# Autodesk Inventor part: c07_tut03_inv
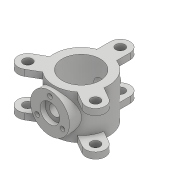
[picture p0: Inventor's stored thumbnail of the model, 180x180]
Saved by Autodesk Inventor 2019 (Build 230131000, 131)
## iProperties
Created: 2017-04
Part Number: c07_tut03_inv
Material: Generic
Document SubType Name: Modeling
Designer: CADCIM 00
Density: 1 g/cm^3
Appearance: Default
Author: CADCIM 00
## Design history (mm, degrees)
sketch "Sketch1"
  geometry: C1 r 140 at (0, 0); C2 r 97 at (0, 0); 1 further point
  constraints: 2 centre point, 2 coincident
  dimensions: "d0" = 280 diameter of C1; "d1" = 194 diameter of C2
extrude "Extrusion1" new body sketch "Sketch1" stored distance "d2" = 225; taper "d3" = 0 deg
workplane "Work Plane1"
sketch "Sketch2"
  geometry: C1 r 100 at (0, 0); 1 further point
  constraints: 1 centre point, 1 coincident
  dimensions: "d5" = 200 diameter of C1
extrude "Extrusion2" join sketch "Sketch2" stored distance "d6" = 225; taper "d7" = 0 deg
workplane "Work Plane2"
sketch "Sketch3"
  geometry: C1 r 37.5 at (0, 0); 1 further point
  constraints: 1 centre point, 1 coincident
  dimensions: "d9" = 75 diameter of C1
extrude "Extrusion3" join sketch "Sketch3" stored distance "d10" = 225; taper "d11" = 0 deg
hole "Hole1" diameter "d14" = 56; stored, may be unused: countersink angle "d18" = 90 deg, drill point angle "d20" = 0 deg; dims "d12" = 10, "d13" = 10, "d15" = 6, "d16" = 100, "d17" = 25, "d19" = 310
sketch "Sketch6"
  geometry: 2 further points
  constraints: 1 vertical alignment
  dimensions: "d21" = 75 distance of point (0, 75) point (0, 0)
hole "Hole2" sketch "Sketch6" at (0, 75) diameter "d22" = 24; stored, may be unused: countersink angle "d26" = 90 deg, drill point angle "d28" = 0 deg; dims "d23" = 6, "d24" = 100, "d25" = 25, "d27" = 15
pattern_circular "Circular Pattern1" dims angle "d30" = 360 deg
sketch "Sketch7"
  geometry: L1 (-50, 130.767)-(-50, 200); L2 (50, 200)-(50, 130.767); L3 (0, 0)-(0, 200); C1 r 23.5 at (0, 200); A1 r 50 centre (0, 200) between (50, 200) and (-50, 200); A2 r 140 centre (0, 0) between (-50, 130.767) and (50, 130.767) reference; 1 further point
  constraints: 6 end point, 4 point on circle, 2 centre point, 2 tangent, 2 vertical, 1 coincident, 1 parallel
  dimensions: "d32" = 200 distance of point (0, 0) L3.end; "d34" = 47 diameter of C1; "d40" = 50 radius of A1
extrude "Extrusion4" join sketch "Sketch7" distance "d35" = 32; taper "d36" = 0 deg
pattern_circular "Circular Pattern2" dims angle "d38" = 360 deg
mirror "Mirror1"
body "Solid1"
other parameters: "d8" = 325
